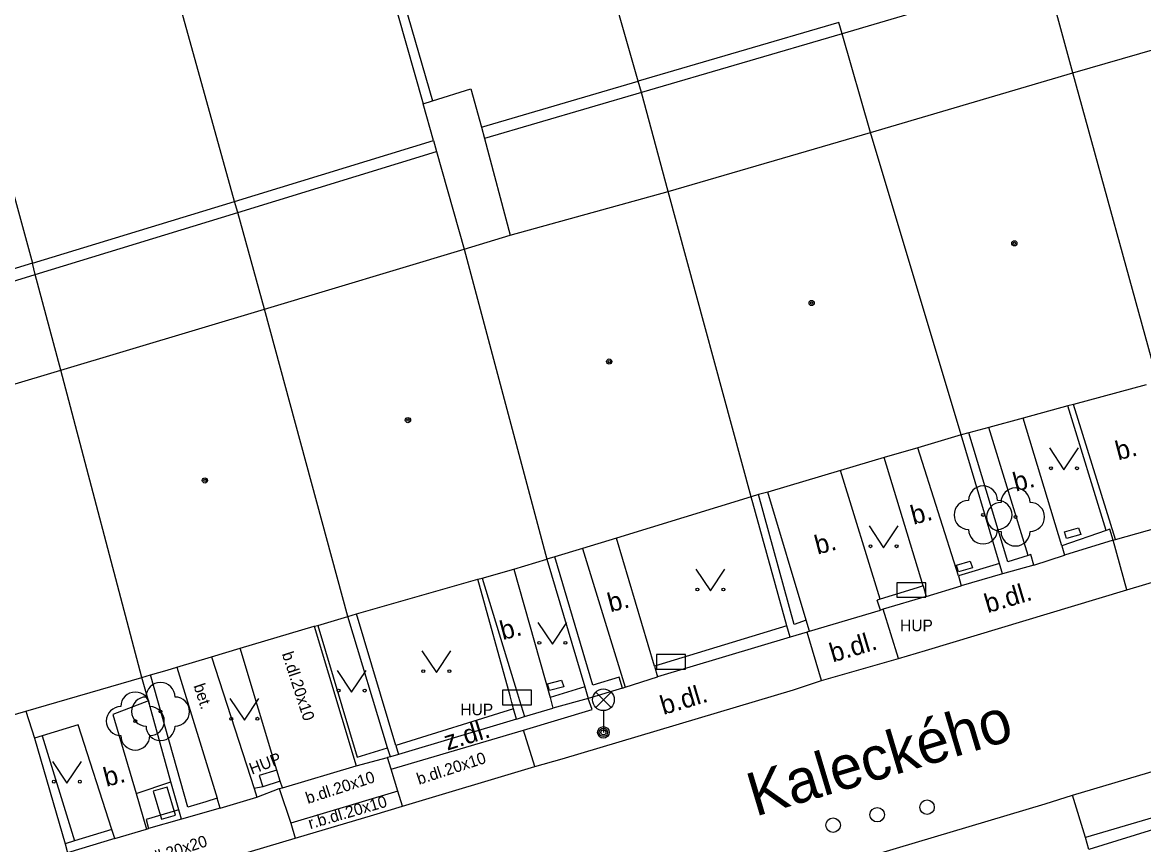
# Model space of a CAD drawing. Extents: x -595546 to -593986, y -1160845 to -1159202.
# Drawn here: x -595512.72 to -595474.06, y -1160590.1 to -1160561.74 of the extents above; entities that cross this region are included whole.
import ezdxf

# ---------------------------------------------------------------- set-up
doc = ezdxf.new("R2010")
doc.units = 0
for name, color, linetype in [('Level 22', 7, 'Continuous'), ('Level 24', 7, 'Continuous'), ('Level 28', 7, 'Continuous'), ('Level 33', 7, 'Continuous'), ('Level 36', 7, 'Continuous'), ('Level 39', 7, 'Continuous'), ('Nazvy ulic', 7, 'Continuous'), ('plynovod - povrch.  znaky - PRIS skut. velikost', 7, 'Continuous'), ('silnoproud - povrch.  znaky a  RIS  skut. velikost', 7, 'Continuous'), ('TM - budovy zdene_ betonove - VP', 7, 'Continuous'), ('TM - chodniky - VP', 7, 'Continuous'), ('TM - komunikace - VP', 7, 'Continuous'), ('TM - letecke snimky - pomocna linie', 7, 'Continuous'), ('TM - plot drateny_ kovovy - VP', 7, 'Continuous'), ('TM - plot dreveny - VP', 7, 'Continuous'), ('TM - plot zdeny_ ohradni zed - VP', 7, 'Continuous'), ('TM - podezdivka plotu - VP', 7, 'Continuous'), ('TM - popis objektu', 7, 'Continuous'), ('TM - popis povrchu', 7, 'Continuous'), ('TM - rozhrani mezi zpev. plochami mezi sebou - VP', 7, 'Continuous'), ('TM - rozhrani ploch obecne - VP', 7, 'Continuous'), ('TM - vjezd na pozemek', 7, 'Continuous'), ('TM - zed operna - VP', 7, 'Continuous')]:
    doc.layers.add(name, color=color, linetype=linetype)

msp = doc.modelspace()

# ---------------------------------------------------------------- linework, layer by layer
at = {"layer": 'Level 22'}
for centre in [(-595479.6, -1160578.73), (-595478.48, -1160578.8), (-595507.96, -1160585.51), (-595508.83, -1160585.84)]:
    msp.add_circle(centre, 0.05, dxfattribs=at)
for centre, start, end in [((-595479.6, -1160578.23), 0, 180), ((-595478.48, -1160578.3), 0, 180), ((-595480.1, -1160578.73), 90, 270), ((-595478.98, -1160578.8), 90, 270), ((-595479.1, -1160578.73), 270, 90), ((-595477.98, -1160578.8), 270, 90), ((-595479.6, -1160579.23), 180, 0), ((-595478.48, -1160579.3), 180, 0), ((-595507.96, -1160585.01), 0, 180), ((-595508.83, -1160585.34), 0, 180), ((-595509.33, -1160585.84), 90, 270), ((-595508.46, -1160585.51), 90, 270), ((-595508.33, -1160585.84), 270, 90), ((-595507.46, -1160585.51), 270, 90), ((-595507.96, -1160586.01), 180, 0), ((-595508.83, -1160586.34), 180, 0)]:
    msp.add_arc(centre, 0.5, start, end, dxfattribs=at)
at = {"layer": 'Level 24'}
for points in [[(-595482.568, -1160581.569), (-595481.568, -1160581.569), (-595481.568, -1160581.069), (-595482.568, -1160581.069)], [(-595490.858, -1160584.049), (-595489.858, -1160584.049), (-595489.858, -1160583.549), (-595490.858, -1160583.549)], [(-595496.168, -1160585.279), (-595495.168, -1160585.279), (-595495.168, -1160584.779), (-595496.168, -1160584.779)], [(-595508.211, -1160588.26), (-595507.929, -1160589.22), (-595507.449, -1160589.08), (-595507.731, -1160588.12)]]:
    msp.add_lwpolyline(points, close=True, dxfattribs=at)
at = {"layer": 'Level 28'}
for centre in [(-595483.25, -1160589.07), (-595481.53, -1160588.81), (-595484.77, -1160589.43)]:
    msp.add_circle(centre, 0.25, dxfattribs=at)
at = {"layer": 'Level 33'}
for p, q in [((-595492.955, -1160585.37), (-595492.425, -1160584.84)), ((-595492.955, -1160584.84), (-595492.425, -1160585.37)), ((-595492.69, -1160585.48), (-595492.69, -1160586.23))]:
    msp.add_line(p, q, dxfattribs=at)
for centre, radius in [((-595492.69, -1160585.105), 0.375), ((-595492.69, -1160586.23), 0.2), ((-595492.69, -1160586.23), 0.145), ((-595492.69, -1160586.23), 0.0876)]:
    msp.add_circle(centre, radius, dxfattribs=at)
at = {"layer": 'Level 36'}
for points in [[(-595477.31, -1160576.42), (-595476.81, -1160577.17), (-595476.31, -1160576.42)], [(-595483.53, -1160579.11), (-595483.03, -1160579.86), (-595482.53, -1160579.11)], [(-595489.5, -1160580.6), (-595489, -1160581.35), (-595488.5, -1160580.6)], [(-595494.95, -1160582.44), (-595494.45, -1160583.19), (-595493.95, -1160582.44)], [(-595498.95, -1160583.42), (-595498.45, -1160584.17), (-595497.95, -1160583.42)], [(-595501.87, -1160584.09), (-595501.37, -1160584.84), (-595500.87, -1160584.09)], [(-595505.57, -1160585.06), (-595505.07, -1160585.81), (-595504.57, -1160585.06)], [(-595511.69, -1160587.23), (-595511.19, -1160587.98), (-595510.69, -1160587.23)]]:
    msp.add_lwpolyline(points, dxfattribs=at)
for centre in [(-595477.26, -1160577.12), (-595476.361, -1160577.12), (-595483.48, -1160579.81), (-595482.581, -1160579.81), (-595489.45, -1160581.3), (-595488.551, -1160581.3), (-595494.9, -1160583.14), (-595494.001, -1160583.14), (-595498.9, -1160584.12), (-595498.001, -1160584.12), (-595501.82, -1160584.79), (-595500.921, -1160584.79), (-595505.52, -1160585.76), (-595504.621, -1160585.76), (-595511.64, -1160587.93), (-595510.741, -1160587.93)]:
    msp.add_circle(centre, 0.05, dxfattribs=at)
at = {"layer": 'Level 39'}
for centre, radius in [((-595478.52, -1160569.36), 0.09), ((-595478.52, -1160569.36), 0.0398), ((-595485.51, -1160571.42), 0.09), ((-595485.51, -1160571.42), 0.0398), ((-595492.49, -1160573.44), 0.09), ((-595492.49, -1160573.44), 0.0398), ((-595499.43, -1160575.46), 0.09), ((-595499.43, -1160575.46), 0.0398), ((-595506.43, -1160577.54), 0.09), ((-595506.43, -1160577.54), 0.0398)]:
    msp.add_circle(centre, radius, dxfattribs=at)
at = {"layer": 'plynovod - povrch.  znaky - PRIS skut. velikost'}
for points in [[(-595476.72, -1160579.54), (-595476.79, -1160579.31), (-595476.31, -1160579.18), (-595476.23, -1160579.41), (-595476.72, -1160579.54)], [(-595503.95, -1160587.53), (-595504.56, -1160587.72)], [(-595503.83, -1160587.91), (-595503.95, -1160587.53)], [(-595504.56, -1160587.72), (-595504.43, -1160588.11)]]:
    msp.add_lwpolyline(points, dxfattribs=at)
at = {"layer": 'silnoproud - povrch.  znaky a  RIS  skut. velikost'}
for points in [[(-595480.45, -1160580.69), (-595480.52, -1160580.46), (-595480.04, -1160580.33), (-595479.96, -1160580.56), (-595480.45, -1160580.69)], [(-595494.55, -1160584.79), (-595494.62, -1160584.56), (-595494.14, -1160584.43), (-595494.06, -1160584.66), (-595494.55, -1160584.79)]]:
    msp.add_lwpolyline(points, dxfattribs=at)
at = {"layer": 'TM - budovy zdene_ betonove - VP'}
for points in [[(-595476.5, -1160563.48), (-595470.17, -1160561.65)], [(-595483.48, -1160565.54), (-595476.5, -1160563.48)], [(-595473.57, -1160574.13), (-595476.5, -1160563.48)], [(-595490.46, -1160567.57), (-595483.48, -1160565.54)], [(-595480.35, -1160575.97), (-595483.48, -1160565.54)], [(-595495.91, -1160569.08), (-595490.46, -1160567.57)], [(-595487.6, -1160578.11), (-595490.46, -1160567.57)], [(-595497.49, -1160569.56), (-595495.91, -1160569.08)], [(-595504.38, -1160571.63), (-595497.49, -1160569.56)], [(-595497.49, -1160569.56), (-595494.64, -1160580.26)], [(-595511.4, -1160573.74), (-595504.38, -1160571.63)], [(-595501.5, -1160582.23), (-595504.38, -1160571.63)], [(-595518.63, -1160575.9), (-595511.4, -1160573.74)], [(-595508.6, -1160584.34), (-595511.4, -1160573.74)], [(-595473.98, -1160574.24), (-595476.48, -1160574.92)], [(-595476.68, -1160574.97), (-595478.22, -1160575.39)], [(-595476.48, -1160574.92), (-595476.68, -1160574.97)], [(-595478.22, -1160575.39), (-595479.4, -1160575.71)], [(-595480.35, -1160575.97), (-595481.85, -1160576.41)], [(-595480.09, -1160575.9), (-595480.35, -1160575.97)], [(-595479.4, -1160575.71), (-595480.09, -1160575.9)], [(-595481.85, -1160576.41), (-595483.01, -1160576.75)], [(-595483.01, -1160576.75), (-595484.52, -1160577.2)], [(-595484.52, -1160577.2), (-595487.02, -1160577.94)], [(-595487.02, -1160577.94), (-595487.34, -1160578.03)], [(-595487.6, -1160578.11), (-595492.24, -1160579.53)], [(-595487.34, -1160578.03), (-595487.6, -1160578.11)], [(-595492.24, -1160579.53), (-595493.41, -1160579.89)], [(-595493.41, -1160579.89), (-595494.37, -1160580.18)], [(-595495.78, -1160580.6), (-595494.64, -1160580.26)], [(-595494.37, -1160580.18), (-595494.64, -1160580.26)], [(-595496.87, -1160580.91), (-595495.78, -1160580.6)], [(-595501.2, -1160582.14), (-595497.02, -1160580.95)], [(-595497.02, -1160580.95), (-595496.87, -1160580.91)], [(-595506.2, -1160583.62), (-595505.21, -1160583.33), (-595502.66, -1160582.57), (-595502.54, -1160582.54), (-595501.5, -1160582.23)], [(-595501.5, -1160582.23), (-595501.2, -1160582.14)], [(-595507.4, -1160583.98), (-595506.2, -1160583.62)], [(-595508.31, -1160584.25), (-595507.73, -1160584.08)], [(-595507.73, -1160584.08), (-595507.4, -1160583.98)], [(-595512.6, -1160585.5), (-595508.6, -1160584.34)], [(-595508.6, -1160584.34), (-595508.31, -1160584.25)], [(-595515.41, -1160586.32), (-595512.6, -1160585.5)]]:
    msp.add_lwpolyline(points, dxfattribs=at)
at = {"layer": 'TM - chodniky - VP'}
for points in [[(-595495.78, -1160580.6), (-595494.53, -1160585.03)], [(-595495.91, -1160584.97), (-595497.02, -1160580.95)], [(-595503.95, -1160587.53), (-595505.21, -1160583.33)], [(-595506.2, -1160583.62), (-595504.73, -1160588.16)], [(-595507.4, -1160583.98), (-595506.01, -1160588.5)], [(-595495.85, -1160585.2), (-595495.91, -1160584.97)], [(-595495.79, -1160585.42), (-595495.85, -1160585.2)], [(-595494.53, -1160585.03), (-595494.43, -1160585.39)], [(-595495.69, -1160585.77), (-595495.79, -1160585.42)]]:
    msp.add_lwpolyline(points, dxfattribs=at)
at = {"layer": 'TM - komunikace - VP'}
for points in [[(-595474.64, -1160581.31), (-595468.86, -1160579.59)], [(-595482.51, -1160583.68), (-595481.59, -1160583.4), (-595475.6, -1160581.6), (-595474.64, -1160581.31)], [(-595485.17, -1160584.44), (-595482.51, -1160583.68)], [(-595495.05, -1160587.41), (-595494.11, -1160587.14), (-595486.13, -1160584.76), (-595485.17, -1160584.44)], [(-595476.51, -1160588.4), (-595469.78, -1160586.4)], [(-595499.62, -1160588.78), (-595495.05, -1160587.41)], [(-595491.28, -1160592.82), (-595490.33, -1160592.53), (-595477.46, -1160588.69), (-595476.51, -1160588.4)], [(-595510.66, -1160592.07), (-595509.68, -1160591.78), (-595503.32, -1160589.88), (-595500.61, -1160589.07), (-595499.62, -1160588.78)]]:
    msp.add_lwpolyline(points, dxfattribs=at)
at = {"layer": 'TM - letecke snimky - pomocna linie'}
msp.add_lwpolyline([(-595499.85, -1160586.68), (-595499.76, -1160586.99)], dxfattribs=at)
at = {"layer": 'TM - plot drateny_ kovovy - VP'}
for points in [[(-595505.41, -1160567.92), (-595509.44, -1160553.38)], [(-595485.7, -1160582.36), (-595486.11, -1160582.51), (-595487.34, -1160578.03)], [(-595492.03, -1160584.7), (-595492.15, -1160584.33), (-595493.05, -1160584.6), (-595494.37, -1160580.18)], [(-595479.03, -1160580.41), (-595480.45, -1160580.83)], [(-595480.45, -1160580.83), (-595480.35, -1160581.18)], [(-595482.32, -1160581.38), (-595483.15, -1160581.64)], [(-595481.84, -1160581.23), (-595482.32, -1160581.38)], [(-595481.67, -1160581.18), (-595481.84, -1160581.23)], [(-595483.15, -1160581.64), (-595483.25, -1160581.67)], [(-595499.85, -1160586.68), (-595501.2, -1160582.14)], [(-595486.36, -1160582.56), (-595490.93, -1160583.95)], [(-595485.58, -1160582.74), (-595485.7, -1160582.36)], [(-595490.93, -1160583.95), (-595490.82, -1160584.31)], [(-595506.4, -1160588.62), (-595507.02, -1160588.81), (-595508.31, -1160584.25)], [(-595493.33, -1160584.66), (-595494.53, -1160585.03)], [(-595495.79, -1160585.42), (-595499.85, -1160586.68)], [(-595504.73, -1160588.16), (-595504.64, -1160588.46)], [(-595506.01, -1160588.5), (-595506.4, -1160588.62)], [(-595505.9, -1160588.84), (-595506.01, -1160588.5)]]:
    msp.add_lwpolyline(points, dxfattribs=at)
at = {"layer": 'TM - plot dreveny - VP'}
for points in [[(-595478.05, -1160580.13), (-595478.75, -1160580.35), (-595480.09, -1160575.9)], [(-595475.36, -1160579.27), (-595476.88, -1160579.79)], [(-595475.11, -1160579.6), (-595475.23, -1160579.22), (-595475.36, -1160579.27)], [(-595476.88, -1160579.79), (-595476.79, -1160580.12)], [(-595477.85, -1160580.46), (-595477.95, -1160580.1), (-595478.05, -1160580.13)]]:
    msp.add_lwpolyline(points, dxfattribs=at)
at = {"layer": 'TM - plot zdeny_ ohradni zed - VP'}
for points in [[(-595502.54, -1160582.54), (-595501.18, -1160587.08)], [(-595501.18, -1160587.08), (-595500.13, -1160586.76)], [(-595503.83, -1160587.91), (-595504.43, -1160588.11)], [(-595504.43, -1160588.11), (-595504.73, -1160588.16)], [(-595507.33, -1160588.9), (-595508.45, -1160589.24), (-595508.37, -1160589.55)], [(-595509.64, -1160589.58), (-595510.93, -1160589.97)], [(-595509.54, -1160589.89), (-595509.64, -1160589.58)], [(-595510.93, -1160589.97), (-595511.25, -1160590.07)], [(-595511.25, -1160590.07), (-595511.17, -1160590.38)]]:
    msp.add_lwpolyline(points, dxfattribs=at)
at = {"layer": 'TM - podezdivka plotu - VP'}
for points in [[(-595479.03, -1160580.41), (-595480.35, -1160575.97)], [(-595486.36, -1160582.56), (-595487.6, -1160578.11)], [(-595475.11, -1160579.6), (-595476.79, -1160580.12)], [(-595494.64, -1160580.26), (-595493.33, -1160584.66)], [(-595478.93, -1160580.76), (-595479.03, -1160580.41)], [(-595477.85, -1160580.46), (-595478.93, -1160580.76)], [(-595478.93, -1160580.76), (-595480.35, -1160581.18)], [(-595481.67, -1160581.18), (-595481.56, -1160581.54)], [(-595483.14, -1160582.01), (-595483.25, -1160581.67)], [(-595481.56, -1160581.54), (-595483.04, -1160581.98)], [(-595500.13, -1160586.76), (-595501.5, -1160582.23)], [(-595483.04, -1160581.98), (-595483.14, -1160582.01)], [(-595502.66, -1160582.57), (-595501.22, -1160587.38)], [(-595486.25, -1160582.95), (-595486.36, -1160582.56)], [(-595486.25, -1160582.95), (-595490.82, -1160584.31)], [(-595485.67, -1160582.77), (-595486.25, -1160582.95)], [(-595485.58, -1160582.74), (-595485.67, -1160582.77)], [(-595508.38, -1160585.14), (-595508.6, -1160584.34)], [(-595493.33, -1160584.66), (-595493.21, -1160585.06)], [(-595492.03, -1160584.7), (-595493.21, -1160585.06)], [(-595507.6, -1160587.93), (-595508.38, -1160585.14)], [(-595493.21, -1160585.06), (-595494.43, -1160585.39)], [(-595495.69, -1160585.77), (-595499.76, -1160586.99)], [(-595500.03, -1160587.07), (-595500.13, -1160586.76)], [(-595501.22, -1160587.38), (-595500.14, -1160587.1)], [(-595500.03, -1160587.07), (-595500.14, -1160587.1)], [(-595499.76, -1160586.99), (-595500.03, -1160587.07)], [(-595507.33, -1160588.9), (-595507.6, -1160587.93)], [(-595503.76, -1160588.14), (-595503.83, -1160587.91)], [(-595504.64, -1160588.46), (-595503.87, -1160588.17)], [(-595503.87, -1160588.17), (-595503.76, -1160588.14)], [(-595507.24, -1160589.22), (-595507.33, -1160588.9)], [(-595505.9, -1160588.84), (-595507.24, -1160589.22)], [(-595507.24, -1160589.22), (-595508.37, -1160589.55)], [(-595509.54, -1160589.89), (-595511.17, -1160590.38)]]:
    msp.add_lwpolyline(points, dxfattribs=at)
at = {"layer": 'TM - rozhrani mezi zpev. plochami mezi sebou - VP'}
for points in [[(-595503.87, -1160588.17), (-595503.47, -1160589.36), (-595503.32, -1160589.88)], [(-595499.78, -1160588.26), (-595503.47, -1160589.36)]]:
    msp.add_lwpolyline(points, dxfattribs=at)
at = {"layer": 'TM - rozhrani ploch obecne - VP'}
for points in [[(-595491.49, -1160563.77), (-595501.6, -1160528.3)], [(-595500.96, -1160557.29), (-595500.64, -1160557.33), (-595498.58, -1160564.45)], [(-595500.96, -1160557.29), (-595498.91, -1160564.55)], [(-595477.43, -1160560.06), (-595484.46, -1160562.13)], [(-595476.5, -1160563.48), (-595477.43, -1160560.06)], [(-595484.57, -1160561.74), (-595491.49, -1160563.77)], [(-595484.46, -1160562.13), (-595484.57, -1160561.74)], [(-595484.46, -1160562.13), (-595491.38, -1160564.16)], [(-595483.48, -1160565.54), (-595484.46, -1160562.13)], [(-595498.58, -1160564.45), (-595497.26, -1160564.03)], [(-595497.26, -1160564.03), (-595496.89, -1160565.36)], [(-595496.89, -1160565.36), (-595491.49, -1160563.77)], [(-595491.38, -1160564.16), (-595491.49, -1160563.77)], [(-595498.91, -1160564.55), (-595498.58, -1160564.45)], [(-595491.38, -1160564.16), (-595496.79, -1160565.75)], [(-595490.46, -1160567.57), (-595491.38, -1160564.16)], [(-595513.81, -1160564.82), (-595512.38, -1160570.05)], [(-595498.55, -1160565.81), (-595498.91, -1160564.55)], [(-595496.89, -1160565.36), (-595496.79, -1160565.75)], [(-595505.41, -1160567.92), (-595498.55, -1160565.81)], [(-595498.55, -1160565.81), (-595498.44, -1160566.19)], [(-595496.79, -1160565.75), (-595495.91, -1160569.08)], [(-595505.3, -1160568.3), (-595498.44, -1160566.19)], [(-595498.44, -1160566.19), (-595497.49, -1160569.56)], [(-595512.38, -1160570.05), (-595505.41, -1160567.92)], [(-595505.3, -1160568.3), (-595505.41, -1160567.92)], [(-595512.28, -1160570.44), (-595505.3, -1160568.3)], [(-595504.38, -1160571.63), (-595505.3, -1160568.3)], [(-595512.38, -1160570.05), (-595519.65, -1160572.28)], [(-595512.28, -1160570.44), (-595512.38, -1160570.05)], [(-595519.54, -1160572.67), (-595512.28, -1160570.44)], [(-595511.4, -1160573.74), (-595512.28, -1160570.44)], [(-595476.88, -1160579.79), (-595478.22, -1160575.39)], [(-595478.05, -1160580.13), (-595479.4, -1160575.71)], [(-595480.45, -1160580.83), (-595481.85, -1160576.41)], [(-595481.67, -1160581.18), (-595483.01, -1160576.75)], [(-595490.93, -1160583.95), (-595492.24, -1160579.53)], [(-595493.41, -1160579.89), (-595491.94, -1160584.67)], [(-595474.64, -1160581.31), (-595475.11, -1160579.6)], [(-595496.87, -1160580.91), (-595495.65, -1160584.9)], [(-595482.51, -1160583.68), (-595483.04, -1160581.98)], [(-595485.17, -1160584.44), (-595485.67, -1160582.77)], [(-595495.65, -1160584.9), (-595495.58, -1160585.13)], [(-595508.38, -1160585.14), (-595509.6, -1160585.61)], [(-595495.58, -1160585.13), (-595495.41, -1160585.68)], [(-595495.44, -1160586.15), (-595493.08, -1160585.44), (-595493.21, -1160585.06)], [(-595509.6, -1160585.61), (-595508.8, -1160588.34)], [(-595510.8, -1160585.97), (-595512.04, -1160586.35)], [(-595509.64, -1160589.58), (-595510.8, -1160585.97)], [(-595512.04, -1160586.35), (-595512.31, -1160586.43)], [(-595512.04, -1160586.35), (-595510.93, -1160589.97)], [(-595500.01, -1160587.5), (-595495.44, -1160586.15)], [(-595495.05, -1160587.41), (-595495.44, -1160586.15)], [(-595500.01, -1160587.5), (-595500.14, -1160587.1)], [(-595503.76, -1160588.14), (-595501.22, -1160587.38)], [(-595499.62, -1160588.78), (-595499.78, -1160588.26), (-595500.01, -1160587.5)], [(-595508.8, -1160588.34), (-595507.6, -1160587.93)], [(-595469.34, -1160587.88), (-595476.07, -1160589.86)], [(-595508.8, -1160588.34), (-595508.44, -1160589.57)], [(-595476.07, -1160589.86), (-595476.51, -1160588.4)], [(-595473.39, -1160589.48), (-595475.95, -1160590.27)], [(-595475.95, -1160590.27), (-595476.07, -1160589.86)]]:
    msp.add_lwpolyline(points, dxfattribs=at)
at = {"layer": 'TM - vjezd na pozemek'}
for points in [[(-595475.03, -1160579.58), (-595472.54, -1160578.88)], [(-595475.11, -1160579.6), (-595475.03, -1160579.58)], [(-595477.85, -1160580.46), (-595476.79, -1160580.12)], [(-595481.56, -1160581.54), (-595480.35, -1160581.18)], [(-595485.58, -1160582.74), (-595483.14, -1160582.01)], [(-595491.94, -1160584.67), (-595490.82, -1160584.31)], [(-595492.03, -1160584.7), (-595491.94, -1160584.67)], [(-595495.69, -1160585.77), (-595495.41, -1160585.68)], [(-595495.41, -1160585.68), (-595494.43, -1160585.39)], [(-595505.9, -1160588.84), (-595504.64, -1160588.46)], [(-595509.54, -1160589.89), (-595508.44, -1160589.57)], [(-595508.44, -1160589.57), (-595508.37, -1160589.55)]]:
    msp.add_lwpolyline(points, dxfattribs=at)
at = {"layer": 'TM - zed operna - VP'}
for points in [[(-595475.36, -1160579.27), (-595476.68, -1160574.97)], [(-595475.03, -1160579.58), (-595476.48, -1160574.92)], [(-595483.15, -1160581.64), (-595484.52, -1160577.2)], [(-595485.7, -1160582.36), (-595487.02, -1160577.94)], [(-595512.6, -1160585.5), (-595512.31, -1160586.43)], [(-595512.31, -1160586.43), (-595511.25, -1160590.07)]]:
    msp.add_lwpolyline(points, dxfattribs=at)

# ---------------------------------------------------------------- texts
at = {"layer": 'Nazvy ulic'}
msp.add_text('Kaleckého', height=1.5, rotation=16.6432, dxfattribs=at).set_placement((-595487.453, -1160589.14))
at = {"layer": 'TM - popis objektu'}
for p in [(-595482.46, -1160582.74), (-595497.62, -1160585.64)]:
    msp.add_text('HUP', height=0.4, dxfattribs=at).set_placement(p)
msp.add_text('HUP', height=0.4, rotation=21, dxfattribs=at).set_placement((-595504.81, -1160587.69))
at = {"layer": 'TM - popis povrchu'}
for s, height, rotation, p in [('b.', 0.65, 14.68, (-595474.94, -1160576.85)), ('b.', 0.65, 14.68, (-595478.47, -1160577.93)), ('b.', 0.65, 14.68, (-595482, -1160579.07)), ('b.', 0.65, 14.68, (-595485.31, -1160580.1)), ('b.dl.', 0.65, 16.57, (-595479.44, -1160582.12)), ('b.', 0.65, 14.68, (-595492.45, -1160582.09)), ('b.', 0.65, 14.68, (-595496.16, -1160583.05)), ('b.dl.', 0.65, 16.57, (-595484.78, -1160583.82)), ('b.dl.20x10', 0.4, 288.0454, (-595503.78, -1160583.52)), ('bet.', 0.4, 288.0454, (-595506.83, -1160584.62)), ('b.dl.', 0.65, 16.57, (-595490.62, -1160585.63)), ('z.dl.', 0.65, 17.38, (-595498.07, -1160586.86)), ('b.dl.20x10', 0.4, 18.0454, (-595499.05, -1160588.04)), ('b.', 0.65, 14.68, (-595509.83, -1160588.11)), ('b.dl.20x10', 0.4, 18.0454, (-595502.88, -1160588.7)), ('r.b.dl.20x10', 0.4, 16.3216, (-595502.8, -1160589.57)), ('b.dl.20x20', 0.4, 18.0454, (-595508.66, -1160590.91))]:
    msp.add_text(s, height=height, rotation=rotation, dxfattribs=at).set_placement(p)

doc.saveas('drawing.dxf')
